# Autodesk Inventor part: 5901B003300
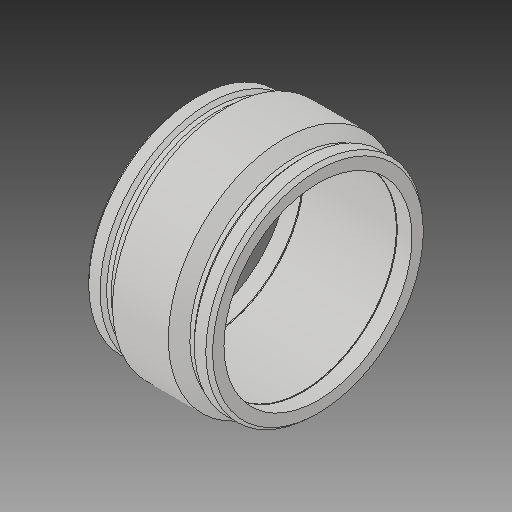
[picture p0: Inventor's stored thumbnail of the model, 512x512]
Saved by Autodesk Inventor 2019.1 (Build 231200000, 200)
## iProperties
Created: 2017-06
Part Number: 5901B003300
Material: Generic
Description: PLASSON IPS COUPLER 30''
Document SubType Name: Modeling
Designer: KIM
Mass: 8622.19 g
Surface Area: 6772.47 cm^2
Volume: 8622.19 cm^3
Density: 1 g/cm^3
Appearance: Default
Author: KIM
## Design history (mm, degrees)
derived "5901B.ipt"
feature "Solid1::5901B.ipt"
tag "TaggingFeature1"
body "Solid1"
other parameters: "d0" = 500.126, "d1" = 758.6, "d2" = 931.926, "d3" = 249.936, "d4" = 125.0315, "d5" = 838.7334, "d6" = 606.88, "d7" = 758.6, "d8" = 168 deg, "d10" = 99.9744, "d11" = 33.3248, "d13" = 500.126, "d14" = 17.6296, "d18" = 758.6, "d19" = 3.52592, "d20" = 168 deg, "d22" = 876.01044, "d23" = 931.926, "d24" = 849.73013, "d25" = 135 deg, "d26" = 225.0567, "d27" = 135 deg, "d29" = 429.006, "d30" = 15, "d31" = 175.0441, "d34" = 5 deg, "d35" = 15, "d39" = 5 deg, "d41" = 4, "d42" = 14, "d43" = 0, "d45" = 4, "d46" = 14, "d47" = 0, "d48" = 3, "d49" = 0, "d50" = 3, "d51" = 0, "d52" = 72.48144, "d53" = 18.12036, "d55" = 249.936, "d_" = 758.6, "L_" = 500.126, "L_1" = 249.936, "D_" = 931.926, "A_" = 429.006, "d_2" = 12, "B_" = 429.006
